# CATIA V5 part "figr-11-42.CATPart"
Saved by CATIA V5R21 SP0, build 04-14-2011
Part number: Part1
Bounding box of the stored display mesh (mm): x -82.6 to 82.6, y -78 to 78, z 0 to 136
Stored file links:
  D:\CATIA V5R21 E-RESOURCES\CATIA-V5R21\catia-v5r21-prt\c11-catia-v5r21-prt\c11-catia-v5r20-figr-11-42.CATPart
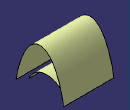
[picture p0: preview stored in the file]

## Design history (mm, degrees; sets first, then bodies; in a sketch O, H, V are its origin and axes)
Set1
  Extrude1: Element1 Sketch1, Lim1 59, Lim2 59, Direction yz-plane
  Affinity1: ToTransfor Extrude1, RatioX 1.4, RatioY 1.3, RatioZ 3.4
Body1 (main body)
  Sketch1 on yz-plane, origin (0, 0, 0), H (0, 1, 0), V (0, 0, 1)
    arc A1 centre (0, -25) radius 65 from (-60, 0) to (60, 0) cw
    point P2 (-60, 0)
    point P3 (60, 0)
    coincidence: P2 H, P3 H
